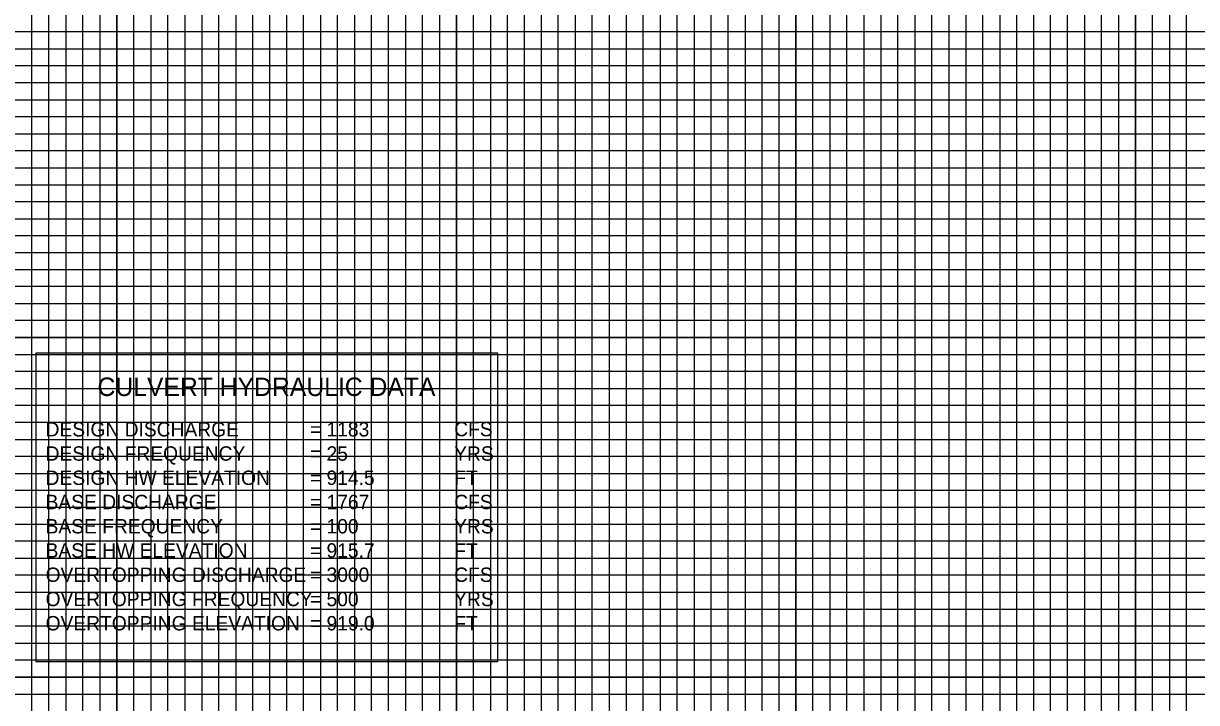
# Model space of a CAD drawing. Extents: x 573624 to 575507, y -53727 to -52273.
# Drawn here: x 574463.3 to 574808.8, y -53180.6 to -52980.6 of the extents above; entities that cross this region are included whole.
import ezdxf

# ---------------------------------------------------------------- set-up
doc = ezdxf.new("R2010")
doc.units = 0
for name, color, linetype in [('Exist Profile Cell', 7, 'Continuous'), ('Prop Grid Mask', 7, 'Continuous'), ('Prop PFL Culvert Hydraulic Data Label CELL', 7, 'Continuous'), ('Sheet DOT Grid CELL', 7, 'Continuous'), ('Sheet Profile Grid Major CELL', 7, 'Continuous'), ('Sheet Profile Grid Middle CELL', 7, 'Continuous'), ('Sheet Profile Grid Minor CELL', 7, 'Continuous')]:
    doc.layers.add(name, color=color, linetype=linetype)

msp = doc.modelspace()

# ---------------------------------------------------------------- linework, layer by layer
at = {"layer": 'Exist Profile Cell'}
msp.add_line((574190.78, -53023.09), (574877.61, -53023.09), dxfattribs=at)
at = {"layer": 'Prop Grid Mask'}
msp.add_line((574485.67, -53092.86), (574485.67, -53092.86), dxfattribs=at)
msp.add_line((574485.67, -53092.86), (574485.67, -53092.86), dxfattribs=at)
msp.add_lwpolyline([(574466.87, -53168.47), (574602.99, -53168.47), (574602.99, -53077.72), (574466.87, -53077.72)], close=True, dxfattribs=at)
at = {"layer": 'Sheet DOT Grid CELL'}
for p, q in [((574490.78, -52298.09), (574490.78, -53323.09)), ((574540.78, -52298.09), (574540.78, -53323.09)), ((574590.78, -52298.09), (574590.78, -53323.09)), ((574640.78, -52298.09), (574640.78, -53323.09)), ((574690.78, -52298.09), (574690.78, -53323.09)), ((574740.78, -52298.09), (574740.78, -53323.09)), ((574790.78, -52298.09), (574790.78, -53323.09)), ((573790.78, -53023.09), (575290.78, -53023.09)), ((573790.78, -53073.09), (575290.78, -53073.09)), ((573790.78, -53123.09), (575290.78, -53123.09)), ((573790.78, -53173.09), (575290.78, -53173.09))]:
    msp.add_line(p, q, dxfattribs=at)
at = {"layer": 'Sheet Profile Grid Major CELL'}
for points in [[(574490.78, -53323.09), (574490.78, -52298.09), (574540.78, -52298.09), (574540.78, -53323.09)], [(574590.78, -53323.09), (574590.78, -52298.09), (574640.78, -52298.09), (574640.78, -53323.09)], [(574690.78, -53323.09), (574690.78, -52298.09), (574740.78, -52298.09), (574740.78, -53323.09)], [(574790.78, -53323.09), (574790.78, -52298.09), (574840.78, -52298.09)], [(575290.78, -53073.09), (573790.78, -53073.09), (573790.78, -53023.09), (575290.78, -53023.09)], [(575290.78, -53173.09), (573790.78, -53173.09), (573790.78, -53123.09), (575290.78, -53123.09)]]:
    msp.add_lwpolyline(points, dxfattribs=at)
at = {"layer": 'Sheet Profile Grid Middle CELL'}
for points in [[(574465.78, -53323.09), (574465.78, -52298.09), (574515.78, -52298.09), (574515.78, -53323.09)], [(574565.78, -53323.09), (574565.78, -52298.09), (574615.78, -52298.09), (574615.78, -53323.09)], [(574665.78, -53323.09), (574665.78, -52298.09), (574715.78, -52298.09), (574715.78, -53323.09)], [(574765.78, -53323.09), (574765.78, -52298.09), (574815.78, -52298.09)], [(575290.78, -52998.09), (573790.78, -52998.09), (573790.78, -53048.09), (575290.78, -53048.09)], [(575290.78, -53098.09), (573790.78, -53098.09), (573790.78, -53148.09), (575290.78, -53148.09)]]:
    msp.add_lwpolyline(points, dxfattribs=at)
at = {"layer": 'Sheet Profile Grid Minor CELL'}
for points in [[(574470.78, -53323.09), (574470.78, -52298.09), (574475.78, -52298.09), (574475.78, -53323.09)], [(574480.78, -53323.09), (574480.78, -52298.09), (574485.78, -52298.09), (574485.78, -53323.09)], [(574495.78, -53323.09), (574495.78, -52298.09), (574500.78, -52298.09), (574500.78, -53323.09)], [(574505.78, -53323.09), (574505.78, -52298.09), (574510.78, -52298.09), (574510.78, -53323.09)], [(574520.78, -53323.09), (574520.78, -52298.09), (574525.78, -52298.09), (574525.78, -53323.09)], [(574530.78, -53323.09), (574530.78, -52298.09), (574535.78, -52298.09), (574535.78, -53323.09)], [(574545.78, -53323.09), (574545.78, -52298.09), (574550.78, -52298.09), (574550.78, -53323.09)], [(574570.78, -53323.09), (574570.78, -52298.09), (574575.78, -52298.09), (574575.78, -53323.09)], [(574580.78, -53323.09), (574580.78, -52298.09), (574585.78, -52298.09), (574585.78, -53323.09)], [(574595.78, -53323.09), (574595.78, -52298.09), (574600.78, -52298.09), (574600.78, -53323.09)], [(574605.78, -53323.09), (574605.78, -52298.09), (574610.78, -52298.09), (574610.78, -53323.09)], [(574620.78, -53323.09), (574620.78, -52298.09), (574625.78, -52298.09), (574625.78, -53323.09)], [(574630.78, -53323.09), (574630.78, -52298.09), (574635.78, -52298.09), (574635.78, -53323.09)], [(574645.78, -53323.09), (574645.78, -52298.09), (574650.78, -52298.09), (574650.78, -53323.09)], [(574655.78, -53323.09), (574655.78, -52298.09), (574660.78, -52298.09), (574660.78, -53323.09)], [(574670.78, -53323.09), (574670.78, -52298.09), (574675.78, -52298.09), (574675.78, -53323.09)], [(574680.78, -53323.09), (574680.78, -52298.09), (574685.78, -52298.09), (574685.78, -53323.09)], [(574695.78, -53323.09), (574695.78, -52298.09), (574700.78, -52298.09), (574700.78, -53323.09)], [(574705.78, -53323.09), (574705.78, -52298.09), (574710.78, -52298.09), (574710.78, -53323.09)], [(574720.78, -53323.09), (574720.78, -52298.09), (574725.78, -52298.09), (574725.78, -53323.09)], [(574730.78, -53323.09), (574730.78, -52298.09), (574735.78, -52298.09), (574735.78, -53323.09)], [(574745.78, -53323.09), (574745.78, -52298.09), (574750.78, -52298.09), (574750.78, -53323.09)], [(574755.78, -53323.09), (574755.78, -52298.09), (574760.78, -52298.09), (574760.78, -53323.09)], [(574770.78, -53323.09), (574770.78, -52298.09), (574775.78, -52298.09), (574775.78, -53323.09)], [(574780.78, -53323.09), (574780.78, -52298.09), (574785.78, -52298.09), (574785.78, -53323.09)], [(574795.78, -53323.09), (574795.78, -52298.09), (574800.78, -52298.09), (574800.78, -53323.09)], [(574805.78, -53323.09), (574805.78, -52298.09), (574810.78, -52298.09)], [(574555.78, -53323.09), (574555.78, -52298.69), (574560.78, -52298.69), (574560.78, -53323.09)], [(575240.78, -52983.09), (573840.78, -52983.09), (573840.78, -52988.09), (575240.78, -52988.09)], [(575240.78, -52993.09), (573840.78, -52993.09), (573840.78, -53003.09), (575240.78, -53003.09)], [(575240.78, -53008.09), (573840.78, -53008.09), (573840.78, -53013.09), (575240.78, -53013.09)], [(575240.78, -53018.09), (573840.78, -53018.09), (573840.78, -53028.09), (575240.78, -53028.09)], [(575240.78, -53033.09), (573840.78, -53033.09), (573840.78, -53038.09), (575240.78, -53038.09)], [(575240.78, -53043.09), (573840.78, -53043.09), (573840.78, -53053.09), (575240.78, -53053.09)], [(575240.78, -53058.09), (573840.78, -53058.09), (573840.78, -53063.09), (575240.78, -53063.09)], [(575240.78, -53068.09), (573840.78, -53068.09), (573840.78, -53078.09), (575240.78, -53078.09)], [(575240.78, -53083.09), (573840.78, -53083.09), (573840.78, -53088.09), (575240.78, -53088.09)], [(575240.78, -53093.09), (573840.78, -53093.09), (573840.78, -53103.09), (575240.78, -53103.09)], [(575240.78, -53108.09), (573840.78, -53108.09), (573840.78, -53113.09), (575240.78, -53113.09)], [(575240.78, -53118.09), (573840.78, -53118.09)], [(573840.78, -53128.09), (575240.78, -53128.09)], [(575240.78, -53133.09), (573840.78, -53133.09), (573840.78, -53138.09), (575240.78, -53138.09)], [(575240.78, -53143.09), (573840.78, -53143.09)], [(573840.78, -53153.09), (575240.78, -53153.09)], [(575240.78, -53158.09), (573840.78, -53158.09), (573840.78, -53163.09), (575240.78, -53163.09)], [(575240.78, -53168.09), (573840.78, -53168.09), (573840.78, -53178.09), (575240.78, -53178.09)]]:
    msp.add_lwpolyline(points, dxfattribs=at)

# ---------------------------------------------------------------- texts
at = {"layer": 'Prop PFL Culvert Hydraulic Data Label CELL'}
for s, height, p in [('CULVERT HYDRAULIC DATA', 5.445, (574485.08, -53090.31)), ('DESIGN DISCHARGE', 4.2349, (574469.79, -53102.23)), ('= 1183', 4.235, (574547.65, -53102.23)), ('CFS', 4.235, (574590.13, -53102.16)), ('DESIGN FREQUENCY', 4.2349, (574469.79, -53109.36)), ('= 25', 4.235, (574547.65, -53109.36)), ('YRS', 4.235, (574590.13, -53109.36)), ('DESIGN HW ELEVATION', 4.2349, (574469.79, -53116.5)), ('= 914.5', 4.235, (574547.65, -53116.5)), ('FT', 4.235, (574590.13, -53116.5)), ('BASE DISCHARGE', 4.2349, (574469.79, -53123.64)), ('= 1767', 4.235, (574547.65, -53123.64)), ('CFS', 4.235, (574590.13, -53123.64)), ('BASE FREQUENCY', 4.2349, (574469.79, -53130.78)), ('= 100', 4.235, (574547.65, -53130.78)), ('YRS', 4.235, (574590.13, -53130.78)), ('BASE HW ELEVATION', 4.2349, (574469.79, -53137.92)), ('= 915.7', 4.235, (574547.65, -53137.92)), ('FT', 4.235, (574590.13, -53137.92)), ('OVERTOPPING DISCHARGE', 4.2349, (574469.79, -53145.06)), ('= 3000', 4.235, (574547.65, -53145.06)), ('CFS', 4.235, (574590.13, -53145.06)), ('OVERTOPPING FREQUENCY', 4.2349, (574469.79, -53152.2)), ('= 500', 4.235, (574547.65, -53152.2)), ('YRS', 4.235, (574590.13, -53152.2)), ('OVERTOPPING ELEVATION', 4.2349, (574469.79, -53159.34)), ('= 919.0', 4.235, (574547.65, -53159.34)), ('FT', 4.235, (574590.13, -53159.34))]:
    msp.add_text(s, height=height, dxfattribs=at).set_placement(p)

doc.saveas('drawing.dxf')
